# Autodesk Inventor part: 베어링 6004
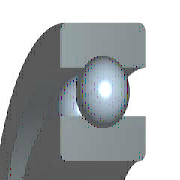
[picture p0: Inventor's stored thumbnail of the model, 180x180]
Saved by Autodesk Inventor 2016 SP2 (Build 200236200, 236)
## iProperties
Created: 2012-02
Part Number: 베어링 6004
Material: 강철, 연강
Description: 깊은 그루브 볼 베어링
Document SubType Name: Modeling
Standard: KS B 2023
Designer: mduedu
Standards Organization: KS
Language: ko-KR
Size Designation: 6004 - 20 x 42 x 12
Categories: <MemberInstance><Categories><Category DisplayName="샤프트 부품" InternalName="7f7aeb1f-a693-4053-b835-cee3144e0d98" Mnemonic="SHFT"><Category DisplayName="베어링" Inter
Density: 1 g/cm^3
Appearance: 노란색
IsCustomPart: 1
Author: mduedu
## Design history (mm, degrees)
sketch "스케치" dims "d0" = 5.72 (= -0.26 x WD + 0.26 x BD)
  geometry: L1 (3.14, 15.5)-(8.86, 15.5); L2 (6, 15.5)-(6, 12.64); L3 (6, 15.5)-(6, 18.36); L4 (3.875, 13.586)-(0, 13.586); L5 (0, 10)-(12, 10); L6 (3.875, 17.414)-(0, 17.414); L7 (0, 21)-(12, 21); L8 (12, 10)-(12, 13.586); L9 (8.125, 13.586)-(12, 13.586); L10 (8.125, 17.414)-(12, 17.414); L11 (12, 21)-(12, 17.414); L12 (-1.4, 0)-(8.4, 0) reference; L13 (0, -0.3)-(0, 5.3) reference
  constraints: 22 end point, 4 point on line, 2 collinear, 2 perpendicular, 2 symmetric about line, 1 midpoint, 1 parallel, 14 other
  dimensions: "d9" = 20 diameter of L5 L12 (= WD); "d11" = 42 diameter of L7 L12 (= BD); "d12" = 12 distance between parallel lines of L8 L13 (= KB); "d13" = 27.172 diameter of L9 L12 (= 0.326 x BD + 0.674 x WD)
revolve "본체" stored, may be unused: angle "d6" = 90 deg
revolve "볼" stored, may be unused: angle "d7" = 90 deg
pattern_circular "IDS_ARRAYBALL[SIMPL:T]" dims angle "d3" = 360 deg
body "Solid1"
fillet "모깎기1" dims "d1" = 0.6 (= KRS)
other parameters: "WD" = 20 [user parameter; used in 5 equation terms], "BD" = 42 [user parameter; used in 5 equation terms], "KB" = 12 [user parameter; used in 1 equation term], "KRS" = 0.6 [user parameter; used in 1 equation term], "d4" = 0, "d5" = 0, "d8" = 0, "d14" = 0, "d15" = 0, "BBA" = 0 [user parameter], "BC0" = 5000000 [user parameter], "BC" = 9360000 [user parameter], "BR" = 21 (= 0.5 x BD) [user parameter]
